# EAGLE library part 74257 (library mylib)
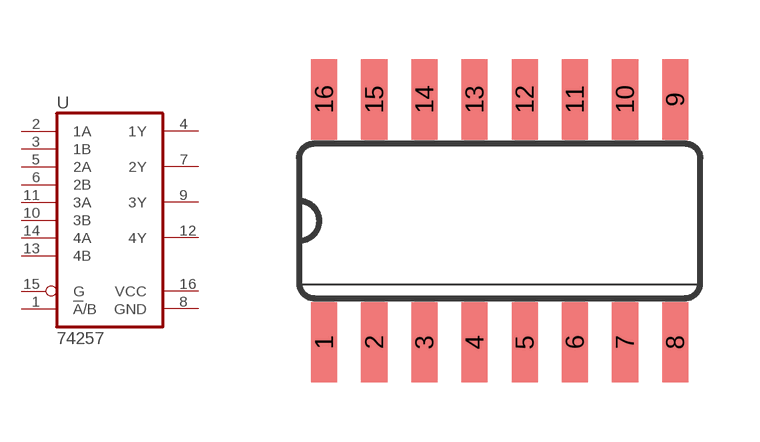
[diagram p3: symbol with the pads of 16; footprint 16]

Designator prefix -

## 74257  [16]
1  !A!/B  in
2  1A  in
3  1B  in
4  1Y  hiz
5  2A  in
6  2B  in
7  2Y  hiz
8  GND
9  3Y  hiz
10  3B  in
11  3A  in
12  4Y  hiz
13  4B  in
14  4A  in
15  G  in
16  VCC

## Footprint 16 (pad centres in mm)
smd 0.66 x 2.032: 1 -4.445,-3.073; 2 -3.175,-3.073; 3 -1.905,-3.073; 4 -0.635,-3.073; 5 0.635,-3.073; 6 1.905,-3.073; 7 3.175,-3.073; 8 4.445,-3.073; 9 4.445,3.073; 10 3.175,3.073; 11 1.905,3.073; 12 0.635,3.073; 13 -0.635,3.073; 14 -1.905,3.073; 15 -3.175,3.073; 16 -4.445,3.073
